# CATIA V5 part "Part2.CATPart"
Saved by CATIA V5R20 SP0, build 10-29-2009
Part number: Part2
Material "DS Light Blue": density 7860 kg/m3, Young's modulus 2e+11 Pa, Poisson ratio 0.266
Bounding box of the stored display mesh (mm): x -25 to 25.2, y -25 to 25, z 0 to 110
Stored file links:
  G:\新建文件夹\Part2.CATPart
  C:\Program Files\Dassault Systemes\B20\win_b64\startup\materials\Catalog.CATMaterial
  C:\Program Files\Dassault Systemes\B20\win_b64\startup\materials\blue_env_512x512.jpg
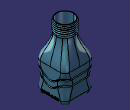
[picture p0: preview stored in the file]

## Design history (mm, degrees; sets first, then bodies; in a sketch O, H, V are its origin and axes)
Set1
  Sketch1 on xy-plane, origin (0, 0, 0), H (1, 0, 0), V (0, 1, 0)
    line L1 (25, 25) -> (25, -25)
    line L2 (25, -25) -> (-25, -25)
    line L3 (-25, -25) -> (-25, 25)
    line L4 (-25, 25) -> (25, 25)
    length L1 = 50
    length L4 = 50
    vertical: L1 V, L3 V
    horizontal: L2 H, L4 H
    equidistance: L1 L3 O, L2 L4 O
Body1 (main body), material "DS Light Blue"
  Pad1: profile Sketch1, direction (0, 0, 1), length 50
  Fillet1: on edge [face of Pad1 from Sketch1.L4 | face of Pad1 from Sketch1.L1]; edge [face of Pad1 from Sketch1.L3 | face of Pad1 from Sketch1.L4]; edge [face of Pad1 from Sketch1.L1 | face of Pad1 from Sketch1.L2]; edge [face of Pad1 from Sketch1.L2 | face of Pad1 from Sketch1.L3]
  Fillet2: radius 8, on start face of Pad1
  Plane1: type Offset, RefPlane end face of Pad1, Offset 40, reversed
  Sketch2 on Plane1, origin (0, 0, 90), H (1, 0, 0), V (0, -1, 0)
    circle A1 centre (0, 0) radius 15
    point P1 (15, 0)
    radius A1 = 15
    coincidence: A1 P1, P1 H
  Pad2: profile Sketch2, direction (0, 0, 1), length 20
  Sketch3 on yz-plane, origin (0, 0, 0), H (0, 1, 0), V (0, 0, 1)
    point P1 (25, 50)
    point P2 (15, 90)
  Loft1: solid, Sections ({boundary Boundary {extract ExtractElem end face of Pad1}}; {boundary Boundary {extract ExtractElem start face of Pad2}}), StartFace end face of Pad1, EndFace start face of Pad2
  Sketch4 on face of Pad1 from Sketch1.L1, origin (25, 0, 0), H (0, 1, 0), V (0, 0, 1)
    spline S1 through (-30, 20) (-20, 30) (0, 20) (20, 30) (30, 20)
  Extrude1: Lim1 55, Lim2 55, Element1 Sketch4
  MultiSel1: CommonCtxFeats ({extract ExtractElem face of Pad1 from Sketch1.L4}; {extract ExtractElem face of Fillet1}; {extract ExtractElem face of Pad1 from Sketch1.L3}; {extract ExtractElem face of Fillet1}; {extract ExtractElem face of Pad1 from Sketch1.L2}; {extract ExtractElem face of Fillet1}; {extract ExtractElem face of Pad1 from Sketch1.L1}; {extract ExtractElem face of Fillet1})
  Sketch5 on face of Pad1 from Sketch1.L1, origin (25, 0, 0), H (0, 1, 0), V (0, 0, 1)
    spline S1 through (-30, 30) (-20, 40) (0, 30) (20, 40) (30, 30)
    point P1 (0, 30)
    coincidence: P1 V
  Extrude2: Lim1 55, Lim2 55, Element1 Sketch5
  MultiSel2: CommonCtxFeats ({extract ExtractElem face of Pad1 from Sketch1.L4}; {extract ExtractElem face of Fillet1}; {extract ExtractElem face of Pad1 from Sketch1.L1}; {extract ExtractElem face of Fillet1}; {extract ExtractElem face of Fillet1}; {extract ExtractElem face of Pad1 from Sketch1.L3}; {extract ExtractElem face of Fillet1}; {extract ExtractElem face of Pad1 from Sketch1.L2})
  Join1: Elements ({intersect ToIntersect1 {extract ExtractElem face of Pad1 from Sketch1.L1}, ToIntersect2 Extrude2}; {intersect ToIntersect1 {extract ExtractElem face of Fillet1}, ToIntersect2 Extrude2}; {intersect ToIntersect1 {extract ExtractElem face of Pad1 from Sketch1.L4}, ToIntersect2 Extrude2}; {intersect ToIntersect1 {extract ExtractElem face of Fillet1}, ToIntersect2 Extrude2}; {intersect ToIntersect1 {extract ExtractElem face of Pad1 from Sketch1.L3}, ToIntersect2 Extrude2}; {intersect ToIntersect1 {extract ExtractElem face of Fillet1}, ToIntersect2 Extrude2}; {intersect ToIntersect1 {extract ExtractElem face of Pad1 from Sketch1.L2}, ToIntersect2 Extrude2}; {intersect ToIntersect1 {extract ExtractElem face of Fillet1}, ToIntersect2 Extrude2})
  Join2: Elements ({intersect ToIntersect1 {extract ExtractElem face of Pad1 from Sketch1.L1}, ToIntersect2 Extrude1}; {intersect ToIntersect1 {extract ExtractElem face of Fillet1}, ToIntersect2 Extrude1}; {intersect ToIntersect1 {extract ExtractElem face of Pad1 from Sketch1.L4}, ToIntersect2 Extrude1}; {intersect ToIntersect1 {extract ExtractElem face of Fillet1}, ToIntersect2 Extrude1}; {intersect ToIntersect1 {extract ExtractElem face of Pad1 from Sketch1.L3}, ToIntersect2 Extrude1}; {intersect ToIntersect1 {extract ExtractElem face of Fillet1}, ToIntersect2 Extrude1}; {intersect ToIntersect1 {extract ExtractElem face of Pad1 from Sketch1.L2}, ToIntersect2 Extrude1}; {intersect ToIntersect1 {extract ExtractElem face of Fillet1}, ToIntersect2 Extrude1})
  Plane2: type Normal, Curve Join1, RefPoint vertex [face of MultiSel2 | face of MultiSel2]
  Circle1: type CtrRad, Start 0, End 180, Radius 1, Center vertex [face of MultiSel2 | face of MultiSel2], Support Plane2, FirstDirection (1, 0, 0)
  Plane3: type Normal, Curve Join2, RefPoint vertex [face of MultiSel1 | face of MultiSel1]
  Circle2: type CtrRad, Start 0, End 180, Radius 1, Center vertex [face of MultiSel1 | face of MultiSel1], Support Plane3, FirstDirection (-1, 0, 0)
  Slot1: profile Circle1, centre curve Join1
  Slot2: profile Circle2, centre curve Join2
  Shell1: IntOffset 1, Face end face of Pad2, ExtOffset 0
  Plane4: type Offset, RefPlane Plane1, Offset 2, reversed
  Sketch6 on Plane4, origin (0, 0, 92), H (1, 0, 0), V (0, -1, 0)
    point P1 (0, -15.0564)
    coincidence: P1 V
  Helix1: Direction Sketch3.V, RefPoint Sketch6, Pitch 3, Height 16, TaperAngle 0
  Line1: type PtDir, RefPoint Sketch6, Direction (0, 1, 0), Start 0, End 10
  Line2: type PtDir, RefPoint vertex of Helix1, Direction (1, 0, 0), Start 0, End 15
  Point1: type OnCurve, Support Helix1, RefPoint Sketch6, Length 5
  Connect1: Curve1 Line1, Point1 vertex of Line1, Tension1 1, Curve2 Helix1, Point2 Point1, Tension2 1
  Point2: type OnCurve, Support Connect1, RefPoint vertex of Line2, Length 5
  Connect2: Curve1 Line2, Point1 vertex of Line2, Tension1 1, Curve2 Connect1, Point2 Point2, Tension2 1
  Plane5: type Normal, Curve Connect2, RefPoint vertex of Connect1
  Circle3: type CtrRad, Start 0, End 180, Radius 1, Center vertex of Connect1, Support Plane5, FirstDirection (-1, 0, 0)
  Plane6: type Normal, Curve Connect2, RefPoint vertex of Connect2
  Circle4: type CtrRad, Start 0, End 180, Radius 1, Center vertex of Connect2, Support Plane6, FirstDirection (0, 1, 0)
  Rib1: profile Circle4, centre curve Connect2
  Body2
    Sketch7 on Plane1, origin (0, 0, 90), H (1, 0, 0), V (0, -1, 0)
      circle A1 centre (0, 0) radius 14
      radius A1 = 14
    Pad3: profile Sketch7, direction (0, 0, 1), length 20
  Remove1: tool Body2
Body3
  Sketch8 on face of Pad1 from Sketch1.L1, origin (25, 0, 0), H (0, 1, 0), V (0, 0, 1)
    polyline C1
    polyline C2
    polyline C3
    polyline C4
    polyline C5
    polyline C6
    polyline C7
    polyline C8
    polyline C9
    polyline C10
    polyline C11
  Pad4: profile Sketch8, direction (1, 0, 0), length 0.2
